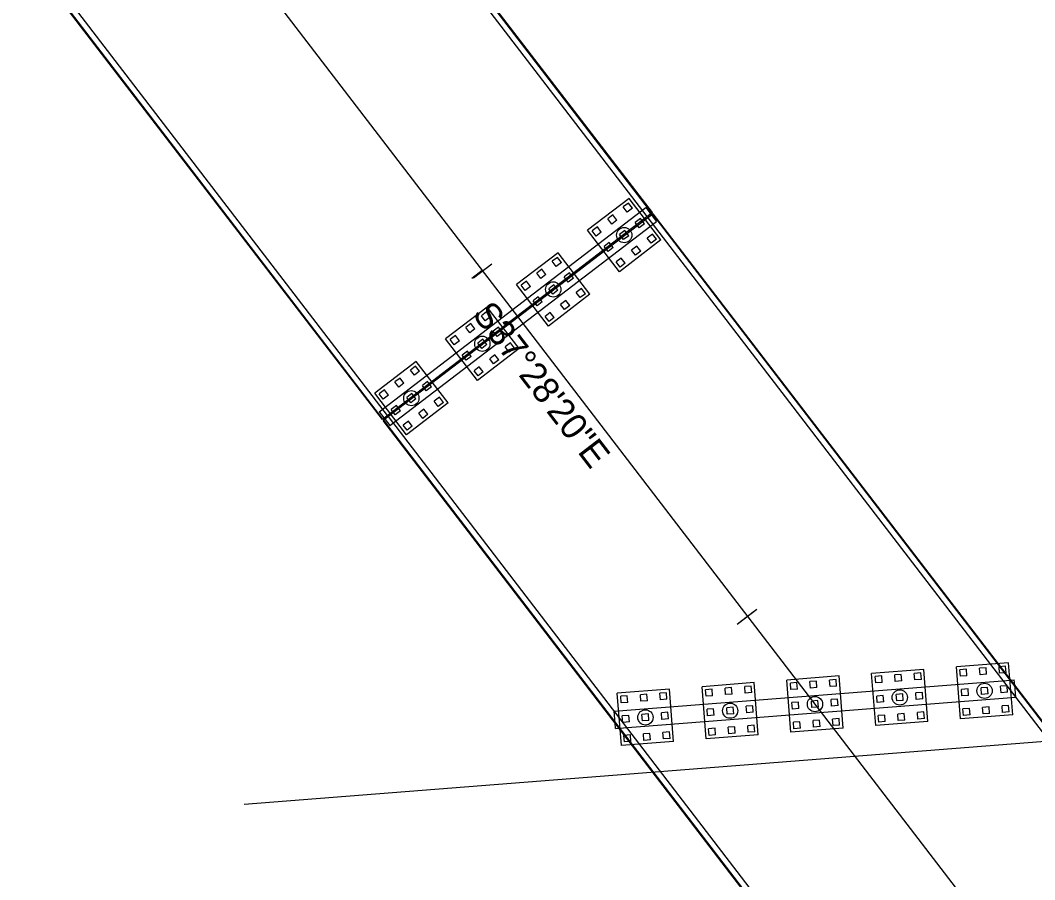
# Model space of a CAD drawing. Extents: x 881426 to 887360, y 1564404 to 1567430.
# Drawn here: x 883927.2 to 884159.8, y 1565449 to 1565646.2 of the extents above; entities that cross this region are included whole.
import ezdxf

# ---------------------------------------------------------------- set-up
doc = ezdxf.new("R2010")
doc.units = 0
for name, color, linetype in [('B_Concrete', 7, 'Continuous'), ('B_Concrete hidden', 7, 'Continuous'), ('R_Horz Alg', 7, 'Continuous'), ('R_Horz Alg Annot', 7, 'Continuous'), ('S_EXIST_ROW', 7, 'Continuous')]:
    doc.layers.add(name, color=color, linetype=linetype)

msp = doc.modelspace()

# ---------------------------------------------------------------- linework, layer by layer
at = {"layer": 'B_Concrete'}
for p, q in [((884070.92, 1565601.14), (883842.93, 1565898.55)), ((884071.97, 1565601.95), (883843.99, 1565899.36)), ((884071.97, 1565601.95), (883843.99, 1565899.36)), ((884072.11, 1565602.05), (883844.12, 1565899.47)), ((884010.2, 1565554.6), (883782.22, 1565852.01)), ((884010.33, 1565554.7), (883782.35, 1565852.11)), ((884010.33, 1565554.7), (883782.35, 1565852.11)), ((884011.39, 1565555.51), (883783.41, 1565852.92)), ((884072.11, 1565602.05), (884010.2, 1565554.6)), ((884072.31, 1565601.79), (884010.4, 1565554.34)), ((884362.37, 1565220.93), (884071.12, 1565600.88)), ((884363.42, 1565221.74), (884072.18, 1565601.69)), ((884363.42, 1565221.74), (884072.18, 1565601.69)), ((884363.56, 1565221.85), (884072.31, 1565601.79)), ((884301.65, 1565174.39), (884010.4, 1565554.34)), ((884301.78, 1565174.49), (884010.54, 1565554.44)), ((884301.78, 1565174.49), (884010.54, 1565554.44)), ((884302.84, 1565175.31), (884011.59, 1565555.25)), ((884154.3, 1565494.82), (884155.1, 1565494.89)), ((884155.19, 1565493.66), (884155.1, 1565494.89)), ((884063.69, 1565483.73), (884063.59, 1565484.95)), ((884063.69, 1565483.73), (884064.48, 1565483.79))]:
    msp.add_line(p, q, dxfattribs=at)
at = {"layer": 'B_Concrete hidden'}
for p, q in [((884066.77, 1565605.31), (884057.25, 1565598.01)), ((884074.07, 1565595.79), (884066.77, 1565605.31)), ((884009.48, 1565556.36), (884070.59, 1565603.2)), ((884066.63, 1565604.26), (884065.44, 1565603.35)), ((884066.35, 1565602.16), (884065.44, 1565603.35)), ((884067.54, 1565603.07), (884066.35, 1565602.16)), ((884067.54, 1565603.07), (884066.63, 1565604.26)), ((884070.59, 1565603.2), (884073.03, 1565600.03)), ((884063.06, 1565601.52), (884061.87, 1565600.61)), ((884062.78, 1565599.42), (884061.87, 1565600.61)), ((884063.97, 1565600.33), (884063.06, 1565601.52)), ((884069.37, 1565600.69), (884068.18, 1565599.78)), ((884070.28, 1565599.5), (884069.37, 1565600.69)), ((884011.92, 1565553.18), (884073.03, 1565600.03)), ((884059.49, 1565598.79), (884058.3, 1565597.87)), ((884060.4, 1565597.6), (884059.49, 1565598.79)), ((884063.97, 1565600.33), (884062.78, 1565599.42)), ((884069.09, 1565598.59), (884068.18, 1565599.78)), ((884070.28, 1565599.5), (884069.09, 1565598.59)), ((884064.55, 1565588.49), (884057.25, 1565598.01)), ((884059.21, 1565596.68), (884058.3, 1565597.87)), ((884060.4, 1565597.6), (884059.21, 1565596.68)), ((884065.8, 1565597.95), (884064.61, 1565597.04)), ((884065.52, 1565595.85), (884064.61, 1565597.04)), ((884066.71, 1565596.76), (884065.52, 1565595.85)), ((884066.71, 1565596.76), (884065.8, 1565597.95)), ((884072.11, 1565597.12), (884070.92, 1565596.21)), ((884071.83, 1565595.02), (884070.92, 1565596.21)), ((884073.02, 1565595.93), (884071.83, 1565595.02)), ((884073.02, 1565595.93), (884072.11, 1565597.12)), ((884062.23, 1565595.22), (884061.04, 1565594.3)), ((884061.95, 1565593.11), (884061.04, 1565594.3)), ((884063.14, 1565594.03), (884061.95, 1565593.11)), ((884063.14, 1565594.03), (884062.23, 1565595.22)), ((884074.07, 1565595.79), (884064.55, 1565588.49)), ((884068.54, 1565594.38), (884067.35, 1565593.47)), ((884069.45, 1565593.19), (884068.54, 1565594.38)), ((884050.5, 1565592.84), (884040.98, 1565585.54)), ((884050.36, 1565591.79), (884049.17, 1565590.88)), ((884051.28, 1565590.6), (884050.36, 1565591.79)), ((884057.8, 1565583.32), (884050.5, 1565592.84)), ((884064.96, 1565591.64), (884063.77, 1565590.73)), ((884065.88, 1565590.45), (884064.96, 1565591.64)), ((884068.26, 1565592.28), (884067.35, 1565593.47)), ((884069.45, 1565593.19), (884068.26, 1565592.28)), ((884046.79, 1565589.05), (884045.6, 1565588.14)), ((884047.7, 1565587.86), (884046.79, 1565589.05)), ((884050.08, 1565589.69), (884049.17, 1565590.88)), ((884051.28, 1565590.6), (884050.08, 1565589.69)), ((884064.69, 1565589.54), (884063.77, 1565590.73)), ((884065.88, 1565590.45), (884064.69, 1565589.54)), ((884046.51, 1565586.95), (884045.6, 1565588.14)), ((884047.7, 1565587.86), (884046.51, 1565586.95)), ((884053.1, 1565588.22), (884051.91, 1565587.31)), ((884052.82, 1565586.12), (884051.91, 1565587.31)), ((884054.01, 1565587.03), (884052.82, 1565586.12)), ((884054.01, 1565587.03), (884053.1, 1565588.22)), ((884048.28, 1565576.02), (884040.98, 1565585.54)), ((884043.22, 1565586.32), (884042.03, 1565585.4)), ((884042.94, 1565584.21), (884042.03, 1565585.4)), ((884044.13, 1565585.13), (884042.94, 1565584.21)), ((884044.13, 1565585.13), (884043.22, 1565586.32)), ((884049.53, 1565585.48), (884048.34, 1565584.57)), ((884049.25, 1565583.38), (884048.34, 1565584.57)), ((884050.44, 1565584.29), (884049.25, 1565583.38)), ((884050.44, 1565584.29), (884049.53, 1565585.48)), ((884055.84, 1565584.65), (884054.65, 1565583.74)), ((884056.75, 1565583.46), (884055.84, 1565584.65)), ((884045.96, 1565582.74), (884044.77, 1565581.83)), ((884046.87, 1565581.55), (884045.96, 1565582.74)), ((884057.8, 1565583.32), (884048.28, 1565576.02)), ((884055.56, 1565582.55), (884054.65, 1565583.74)), ((884056.75, 1565583.46), (884055.56, 1565582.55)), ((884034.23, 1565580.37), (884024.71, 1565573.07)), ((884041.53, 1565570.85), (884034.23, 1565580.37)), ((884045.68, 1565580.64), (884044.77, 1565581.83)), ((884046.87, 1565581.55), (884045.68, 1565580.64)), ((884052.27, 1565581.91), (884051.08, 1565581)), ((884051.99, 1565579.81), (884051.08, 1565581)), ((884053.18, 1565580.72), (884051.99, 1565579.81)), ((884053.18, 1565580.72), (884052.27, 1565581.91)), ((884034.09, 1565579.32), (884032.9, 1565578.41)), ((884033.81, 1565577.22), (884032.9, 1565578.41)), ((884035.01, 1565578.13), (884033.81, 1565577.22)), ((884035.01, 1565578.13), (884034.09, 1565579.32)), ((884048.69, 1565579.17), (884047.5, 1565578.26)), ((884048.42, 1565577.07), (884047.5, 1565578.26)), ((884049.61, 1565577.98), (884048.42, 1565577.07)), ((884049.61, 1565577.98), (884048.69, 1565579.17)), ((884030.52, 1565576.58), (884029.33, 1565575.67)), ((884030.24, 1565574.48), (884029.33, 1565575.67)), ((884031.43, 1565575.39), (884030.24, 1565574.48)), ((884031.43, 1565575.39), (884030.52, 1565576.58)), ((884036.83, 1565575.75), (884035.64, 1565574.84)), ((884037.74, 1565574.56), (884036.83, 1565575.75)), ((884032.01, 1565563.55), (884024.71, 1565573.07)), ((884026.95, 1565573.84), (884025.76, 1565572.93)), ((884026.67, 1565571.74), (884025.76, 1565572.93)), ((884027.86, 1565572.65), (884026.67, 1565571.74)), ((884027.86, 1565572.65), (884026.95, 1565573.84)), ((884033.26, 1565573.01), (884032.07, 1565572.1)), ((884034.17, 1565571.82), (884033.26, 1565573.01)), ((884036.55, 1565573.64), (884035.64, 1565574.84)), ((884037.74, 1565574.56), (884036.55, 1565573.64)), ((884041.53, 1565570.85), (884032.01, 1565563.55)), ((884032.98, 1565570.91), (884032.07, 1565572.1)), ((884034.17, 1565571.82), (884032.98, 1565570.91)), ((884039.57, 1565572.18), (884038.38, 1565571.26)), ((884039.29, 1565570.07), (884038.38, 1565571.26)), ((884040.48, 1565570.99), (884039.29, 1565570.07)), ((884040.48, 1565570.99), (884039.57, 1565572.18)), ((884029.69, 1565570.27), (884028.5, 1565569.36)), ((884029.41, 1565568.17), (884028.5, 1565569.36)), ((884030.6, 1565569.08), (884029.41, 1565568.17)), ((884030.6, 1565569.08), (884029.69, 1565570.27)), ((884036, 1565569.44), (884034.81, 1565568.53)), ((884035.72, 1565567.34), (884034.81, 1565568.53)), ((884036.91, 1565568.25), (884035.72, 1565567.34)), ((884036.91, 1565568.25), (884036, 1565569.44)), ((884017.96, 1565567.9), (884008.44, 1565560.6)), ((884017.82, 1565566.85), (884016.63, 1565565.93)), ((884017.54, 1565564.74), (884016.63, 1565565.93)), ((884018.74, 1565565.66), (884017.82, 1565566.85)), ((884025.26, 1565558.38), (884017.96, 1565567.9)), ((884032.43, 1565566.7), (884031.23, 1565565.79)), ((884032.15, 1565564.6), (884031.23, 1565565.79)), ((884033.34, 1565565.51), (884032.43, 1565566.7)), ((884014.25, 1565564.11), (884013.06, 1565563.2)), ((884015.16, 1565562.92), (884014.25, 1565564.11)), ((884018.74, 1565565.66), (884017.54, 1565564.74)), ((884033.34, 1565565.51), (884032.15, 1565564.6)), ((884010.68, 1565561.37), (884009.49, 1565560.46)), ((884011.59, 1565560.18), (884010.68, 1565561.37)), ((884013.97, 1565562.01), (884013.06, 1565563.2)), ((884015.16, 1565562.92), (884013.97, 1565562.01)), ((884020.56, 1565563.28), (884019.37, 1565562.36)), ((884020.28, 1565561.17), (884019.37, 1565562.36)), ((884021.47, 1565562.09), (884020.28, 1565561.17)), ((884021.47, 1565562.09), (884020.56, 1565563.28)), ((884015.74, 1565551.07), (884008.44, 1565560.6)), ((884010.4, 1565559.27), (884009.49, 1565560.46)), ((884011.59, 1565560.18), (884010.4, 1565559.27)), ((884016.99, 1565560.54), (884015.8, 1565559.63)), ((884016.71, 1565558.44), (884015.8, 1565559.63)), ((884017.9, 1565559.35), (884016.71, 1565558.44)), ((884017.9, 1565559.35), (884016.99, 1565560.54)), ((884023.3, 1565559.7), (884022.11, 1565558.79)), ((884023.02, 1565557.6), (884022.11, 1565558.79)), ((884024.21, 1565558.51), (884023.3, 1565559.7)), ((884013.42, 1565557.8), (884012.23, 1565556.89)), ((884013.14, 1565555.7), (884012.23, 1565556.89)), ((884014.33, 1565556.61), (884013.14, 1565555.7)), ((884014.33, 1565556.61), (884013.42, 1565557.8)), ((884025.26, 1565558.38), (884015.74, 1565551.07)), ((884019.73, 1565556.97), (884018.54, 1565556.05)), ((884020.64, 1565555.78), (884019.73, 1565556.97)), ((884024.21, 1565558.51), (884023.02, 1565557.6)), ((884009.48, 1565556.36), (884011.92, 1565553.18)), ((884016.16, 1565554.23), (884014.96, 1565553.32)), ((884017.07, 1565553.04), (884016.16, 1565554.23)), ((884019.45, 1565554.86), (884018.54, 1565556.05)), ((884020.64, 1565555.78), (884019.45, 1565554.86)), ((884015.88, 1565552.13), (884014.96, 1565553.32)), ((884017.07, 1565553.04), (884015.88, 1565552.13)), ((884153.79, 1565498.8), (884141.82, 1565497.86)), ((884154.72, 1565486.83), (884153.79, 1565498.8)), ((884134.35, 1565497.28), (884122.38, 1565496.34)), ((884123.32, 1565484.38), (884122.38, 1565496.34)), ((884129.17, 1565496.12), (884127.68, 1565496)), ((884127.79, 1565494.51), (884127.68, 1565496)), ((884129.29, 1565494.62), (884129.17, 1565496.12)), ((884133.66, 1565496.47), (884132.16, 1565496.35)), ((884132.28, 1565494.86), (884132.16, 1565496.35)), ((884133.78, 1565494.97), (884133.66, 1565496.47)), ((884135.28, 1565485.31), (884134.35, 1565497.28)), ((884142.76, 1565485.9), (884141.82, 1565497.86)), ((884144.13, 1565497.29), (884142.63, 1565497.17)), ((884142.75, 1565495.68), (884142.63, 1565497.17)), ((884144.24, 1565495.79), (884144.13, 1565497.29)), ((884148.61, 1565497.64), (884147.12, 1565497.52)), ((884147.23, 1565496.03), (884147.12, 1565497.52)), ((884148.73, 1565496.14), (884147.23, 1565496.03)), ((884148.73, 1565496.14), (884148.61, 1565497.64)), ((884153.1, 1565497.99), (884151.6, 1565497.87)), ((884151.72, 1565496.38), (884151.6, 1565497.87)), ((884153.22, 1565496.49), (884151.72, 1565496.38)), ((884153.22, 1565496.49), (884153.1, 1565497.99)), ((884063.38, 1565487.71), (884154.3, 1565494.82)), ((884095.47, 1565494.23), (884083.5, 1565493.3)), ((884096.4, 1565482.27), (884095.47, 1565494.23)), ((884114.91, 1565495.76), (884102.94, 1565494.82)), ((884103.88, 1565482.86), (884102.94, 1565494.82)), ((884105.25, 1565494.25), (884103.75, 1565494.13)), ((884103.87, 1565492.64), (884103.75, 1565494.13)), ((884105.36, 1565492.75), (884105.25, 1565494.25)), ((884109.73, 1565494.6), (884108.24, 1565494.48)), ((884108.35, 1565492.99), (884108.24, 1565494.48)), ((884109.85, 1565493.1), (884109.73, 1565494.6)), ((884114.22, 1565494.95), (884112.72, 1565494.83)), ((884112.84, 1565493.34), (884112.72, 1565494.83)), ((884114.33, 1565493.45), (884114.22, 1565494.95)), ((884115.84, 1565483.79), (884114.91, 1565495.76)), ((884124.69, 1565495.77), (884123.19, 1565495.65)), ((884123.31, 1565494.16), (884123.19, 1565495.65)), ((884124.8, 1565494.27), (884123.31, 1565494.16)), ((884124.8, 1565494.27), (884124.69, 1565495.77)), ((884129.29, 1565494.62), (884127.79, 1565494.51)), ((884133.78, 1565494.97), (884132.28, 1565494.86)), ((884144.24, 1565495.79), (884142.75, 1565495.68)), ((884155.41, 1565490.9), (884155.19, 1565493.66)), ((884076.03, 1565492.71), (884064.06, 1565491.78)), ((884065, 1565479.82), (884064.06, 1565491.78)), ((884070.85, 1565491.56), (884069.35, 1565491.44)), ((884069.47, 1565489.94), (884069.35, 1565491.44)), ((884070.97, 1565490.06), (884070.85, 1565491.56)), ((884075.34, 1565491.91), (884073.84, 1565491.79)), ((884073.96, 1565490.3), (884073.84, 1565491.79)), ((884075.45, 1565490.41), (884075.34, 1565491.91)), ((884076.96, 1565480.75), (884076.03, 1565492.71)), ((884084.44, 1565481.34), (884083.5, 1565493.3)), ((884085.8, 1565492.73), (884084.31, 1565492.61)), ((884084.43, 1565491.11), (884084.31, 1565492.61)), ((884085.92, 1565491.23), (884085.8, 1565492.73)), ((884090.29, 1565493.08), (884088.8, 1565492.96)), ((884088.91, 1565491.47), (884088.8, 1565492.96)), ((884090.41, 1565491.58), (884088.91, 1565491.47)), ((884090.41, 1565491.58), (884090.29, 1565493.08)), ((884094.78, 1565493.43), (884093.28, 1565493.31)), ((884093.4, 1565491.82), (884093.28, 1565493.31)), ((884094.89, 1565491.93), (884093.4, 1565491.82)), ((884094.89, 1565491.93), (884094.78, 1565493.43)), ((884105.36, 1565492.75), (884103.87, 1565492.64)), ((884109.85, 1565493.1), (884108.35, 1565492.99)), ((884114.33, 1565493.45), (884112.84, 1565493.34)), ((884125.04, 1565491.28), (884123.54, 1565491.16)), ((884125.15, 1565489.79), (884125.04, 1565491.28)), ((884129.52, 1565491.63), (884128.03, 1565491.52)), ((884128.14, 1565490.02), (884128.03, 1565491.52)), ((884129.64, 1565490.14), (884129.52, 1565491.63)), ((884134.01, 1565491.98), (884132.51, 1565491.87)), ((884132.63, 1565490.37), (884132.51, 1565491.87)), ((884134.13, 1565490.49), (884134.01, 1565491.98)), ((884144.48, 1565492.8), (884142.98, 1565492.69)), ((884143.1, 1565491.19), (884142.98, 1565492.69)), ((884144.59, 1565491.31), (884143.1, 1565491.19)), ((884144.59, 1565491.31), (884144.48, 1565492.8)), ((884148.96, 1565493.15), (884147.47, 1565493.04)), ((884147.59, 1565491.54), (884147.47, 1565493.04)), ((884149.08, 1565491.66), (884147.59, 1565491.54)), ((884149.08, 1565491.66), (884148.96, 1565493.15)), ((884153.45, 1565493.5), (884151.95, 1565493.39)), ((884152.07, 1565491.89), (884151.95, 1565493.39)), ((884153.57, 1565492.01), (884152.07, 1565491.89)), ((884153.57, 1565492.01), (884153.45, 1565493.5)), ((884064.48, 1565483.79), (884155.41, 1565490.9)), ((884066.36, 1565491.21), (884064.87, 1565491.09)), ((884064.99, 1565489.59), (884064.87, 1565491.09)), ((884066.48, 1565489.71), (884064.99, 1565489.59)), ((884066.48, 1565489.71), (884066.36, 1565491.21)), ((884070.97, 1565490.06), (884069.47, 1565489.94)), ((884075.45, 1565490.41), (884073.96, 1565490.3)), ((884085.92, 1565491.23), (884084.43, 1565491.11)), ((884095.13, 1565488.94), (884093.63, 1565488.83)), ((884095.24, 1565487.45), (884095.13, 1565488.94)), ((884105.6, 1565489.76), (884104.1, 1565489.64)), ((884104.22, 1565488.15), (884104.1, 1565489.64)), ((884105.71, 1565488.27), (884105.6, 1565489.76)), ((884110.08, 1565490.11), (884108.59, 1565490)), ((884108.7, 1565488.5), (884108.59, 1565490)), ((884110.2, 1565488.62), (884110.08, 1565490.11)), ((884114.57, 1565490.46), (884113.07, 1565490.35)), ((884113.19, 1565488.85), (884113.07, 1565490.35)), ((884114.69, 1565488.97), (884113.19, 1565488.85)), ((884114.69, 1565488.97), (884114.57, 1565490.46)), ((884123.66, 1565489.67), (884123.54, 1565491.16)), ((884125.15, 1565489.79), (884123.66, 1565489.67)), ((884129.64, 1565490.14), (884128.14, 1565490.02)), ((884134.13, 1565490.49), (884132.63, 1565490.37)), ((884153.8, 1565489.02), (884152.31, 1565488.9)), ((884153.92, 1565487.52), (884153.8, 1565489.02)), ((884063.59, 1565484.95), (884063.38, 1565487.71)), ((884066.71, 1565486.72), (884065.22, 1565486.6)), ((884065.34, 1565485.11), (884065.22, 1565486.6)), ((884066.83, 1565485.22), (884066.71, 1565486.72)), ((884071.2, 1565487.07), (884069.71, 1565486.95)), ((884069.82, 1565485.46), (884069.71, 1565486.95)), ((884071.32, 1565485.58), (884071.2, 1565487.07)), ((884075.69, 1565487.42), (884074.19, 1565487.3)), ((884074.31, 1565485.81), (884074.19, 1565487.3)), ((884075.8, 1565485.93), (884075.69, 1565487.42)), ((884086.16, 1565488.24), (884084.66, 1565488.12)), ((884084.78, 1565486.63), (884084.66, 1565488.12)), ((884086.27, 1565486.75), (884084.78, 1565486.63)), ((884086.27, 1565486.75), (884086.16, 1565488.24)), ((884090.64, 1565488.59), (884089.15, 1565488.47)), ((884089.26, 1565486.98), (884089.15, 1565488.47)), ((884090.76, 1565487.1), (884089.26, 1565486.98)), ((884090.76, 1565487.1), (884090.64, 1565488.59)), ((884093.75, 1565487.33), (884093.63, 1565488.83)), ((884095.24, 1565487.45), (884093.75, 1565487.33)), ((884105.71, 1565488.27), (884104.22, 1565488.15)), ((884110.2, 1565488.62), (884108.7, 1565488.5)), ((884125.39, 1565486.8), (884123.89, 1565486.68)), ((884124.01, 1565485.18), (884123.89, 1565486.68)), ((884125.5, 1565485.3), (884125.39, 1565486.8)), ((884129.87, 1565487.15), (884128.38, 1565487.03)), ((884128.5, 1565485.53), (884128.38, 1565487.03)), ((884129.99, 1565485.65), (884129.87, 1565487.15)), ((884134.36, 1565487.5), (884132.86, 1565487.38)), ((884132.98, 1565485.88), (884132.86, 1565487.38)), ((884134.48, 1565486), (884134.36, 1565487.5)), ((884154.72, 1565486.83), (884142.76, 1565485.9)), ((884144.83, 1565488.32), (884143.33, 1565488.2)), ((884143.45, 1565486.7), (884143.33, 1565488.2)), ((884144.95, 1565486.82), (884143.45, 1565486.7)), ((884144.95, 1565486.82), (884144.83, 1565488.32)), ((884149.31, 1565488.67), (884147.82, 1565488.55)), ((884147.94, 1565487.05), (884147.82, 1565488.55)), ((884149.43, 1565487.17), (884147.94, 1565487.05)), ((884149.43, 1565487.17), (884149.31, 1565488.67)), ((884152.42, 1565487.41), (884152.31, 1565488.9)), ((884153.92, 1565487.52), (884152.42, 1565487.41)), ((884066.83, 1565485.22), (884065.34, 1565485.11)), ((884071.32, 1565485.58), (884069.82, 1565485.46)), ((884075.8, 1565485.93), (884074.31, 1565485.81)), ((884095.48, 1565484.46), (884093.98, 1565484.34)), ((884094.1, 1565482.84), (884093.98, 1565484.34)), ((884095.6, 1565482.96), (884095.48, 1565484.46)), ((884105.95, 1565485.27), (884104.45, 1565485.16)), ((884104.57, 1565483.66), (884104.45, 1565485.16)), ((884106.06, 1565483.78), (884105.95, 1565485.27)), ((884110.43, 1565485.63), (884108.94, 1565485.51)), ((884109.05, 1565484.01), (884108.94, 1565485.51)), ((884110.55, 1565484.13), (884110.43, 1565485.63)), ((884114.92, 1565485.98), (884113.42, 1565485.86)), ((884113.54, 1565484.36), (884113.42, 1565485.86)), ((884115.04, 1565484.48), (884113.54, 1565484.36)), ((884115.04, 1565484.48), (884114.92, 1565485.98)), ((884135.28, 1565485.31), (884123.32, 1565484.38)), ((884125.5, 1565485.3), (884124.01, 1565485.18)), ((884129.99, 1565485.65), (884128.5, 1565485.53)), ((884134.48, 1565486), (884132.98, 1565485.88)), ((884067.07, 1565482.23), (884065.57, 1565482.12)), ((884065.69, 1565480.62), (884065.57, 1565482.12)), ((884067.18, 1565480.74), (884067.07, 1565482.23)), ((884071.55, 1565482.58), (884070.06, 1565482.47)), ((884070.17, 1565480.97), (884070.06, 1565482.47)), ((884071.67, 1565481.09), (884071.55, 1565482.58)), ((884076.04, 1565482.94), (884074.54, 1565482.82)), ((884074.66, 1565481.32), (884074.54, 1565482.82)), ((884076.16, 1565481.44), (884076.04, 1565482.94)), ((884096.4, 1565482.27), (884084.44, 1565481.34)), ((884086.51, 1565483.75), (884085.01, 1565483.64)), ((884085.13, 1565482.14), (884085.01, 1565483.64)), ((884086.62, 1565482.26), (884085.13, 1565482.14)), ((884086.62, 1565482.26), (884086.51, 1565483.75)), ((884090.99, 1565484.11), (884089.5, 1565483.99)), ((884089.61, 1565482.49), (884089.5, 1565483.99)), ((884091.11, 1565482.61), (884089.61, 1565482.49)), ((884091.11, 1565482.61), (884090.99, 1565484.11)), ((884095.6, 1565482.96), (884094.1, 1565482.84)), ((884115.84, 1565483.79), (884103.88, 1565482.86)), ((884106.06, 1565483.78), (884104.57, 1565483.66)), ((884110.55, 1565484.13), (884109.05, 1565484.01)), ((884076.96, 1565480.75), (884065, 1565479.82)), ((884067.18, 1565480.74), (884065.69, 1565480.62)), ((884071.67, 1565481.09), (884070.17, 1565480.97)), ((884076.16, 1565481.44), (884074.66, 1565481.32))]:
    msp.add_line(p, q, dxfattribs=at)
for centre in [(884065.66, 1565596.9), (884049.39, 1565584.43), (884033.12, 1565571.96), (884016.85, 1565559.49), (884148.27, 1565492.35), (884128.83, 1565490.83), (884089.95, 1565487.79), (884109.39, 1565489.31), (884070.51, 1565486.26)]:
    msp.add_circle(centre, 1.75, dxfattribs=at)
at = {"layer": 'R_Horz Alg'}
msp.add_line((883399.11, 1566415.89), (884332.67, 1565198.04), dxfattribs=at)
at = {"layer": 'R_Horz Alg Annot'}
for p, q in [((884031.08, 1565587.09), (884035.31, 1565590.33)), ((884091.83, 1565507.84), (884096.06, 1565511.08)), ((884092.35, 1565508.25), (884095.53, 1565510.68))]:
    msp.add_line(p, q, dxfattribs=at)
for points in [[(884030.72, 1565587), (884033.1, 1565588.83)], [(884091.56, 1565507.64), (884093.94, 1565509.46)]]:
    msp.add_lwpolyline(points, dxfattribs=at)
at = {"layer": 'S_EXIST_ROW'}
msp.add_line((884266.26, 1565488.87), (883978.5, 1565466.31), dxfattribs=at)

# ---------------------------------------------------------------- texts
at = {"layer": 'R_Horz Alg Annot'}
msp.add_text('S37%%d28\'20"E', height=6, rotation=307.4722, dxfattribs=at).set_placement((884030.63, 1565578.7))

doc.saveas('drawing.dxf')
